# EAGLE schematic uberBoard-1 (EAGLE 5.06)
ABBREV: un1; PROJECT: UberNode v1
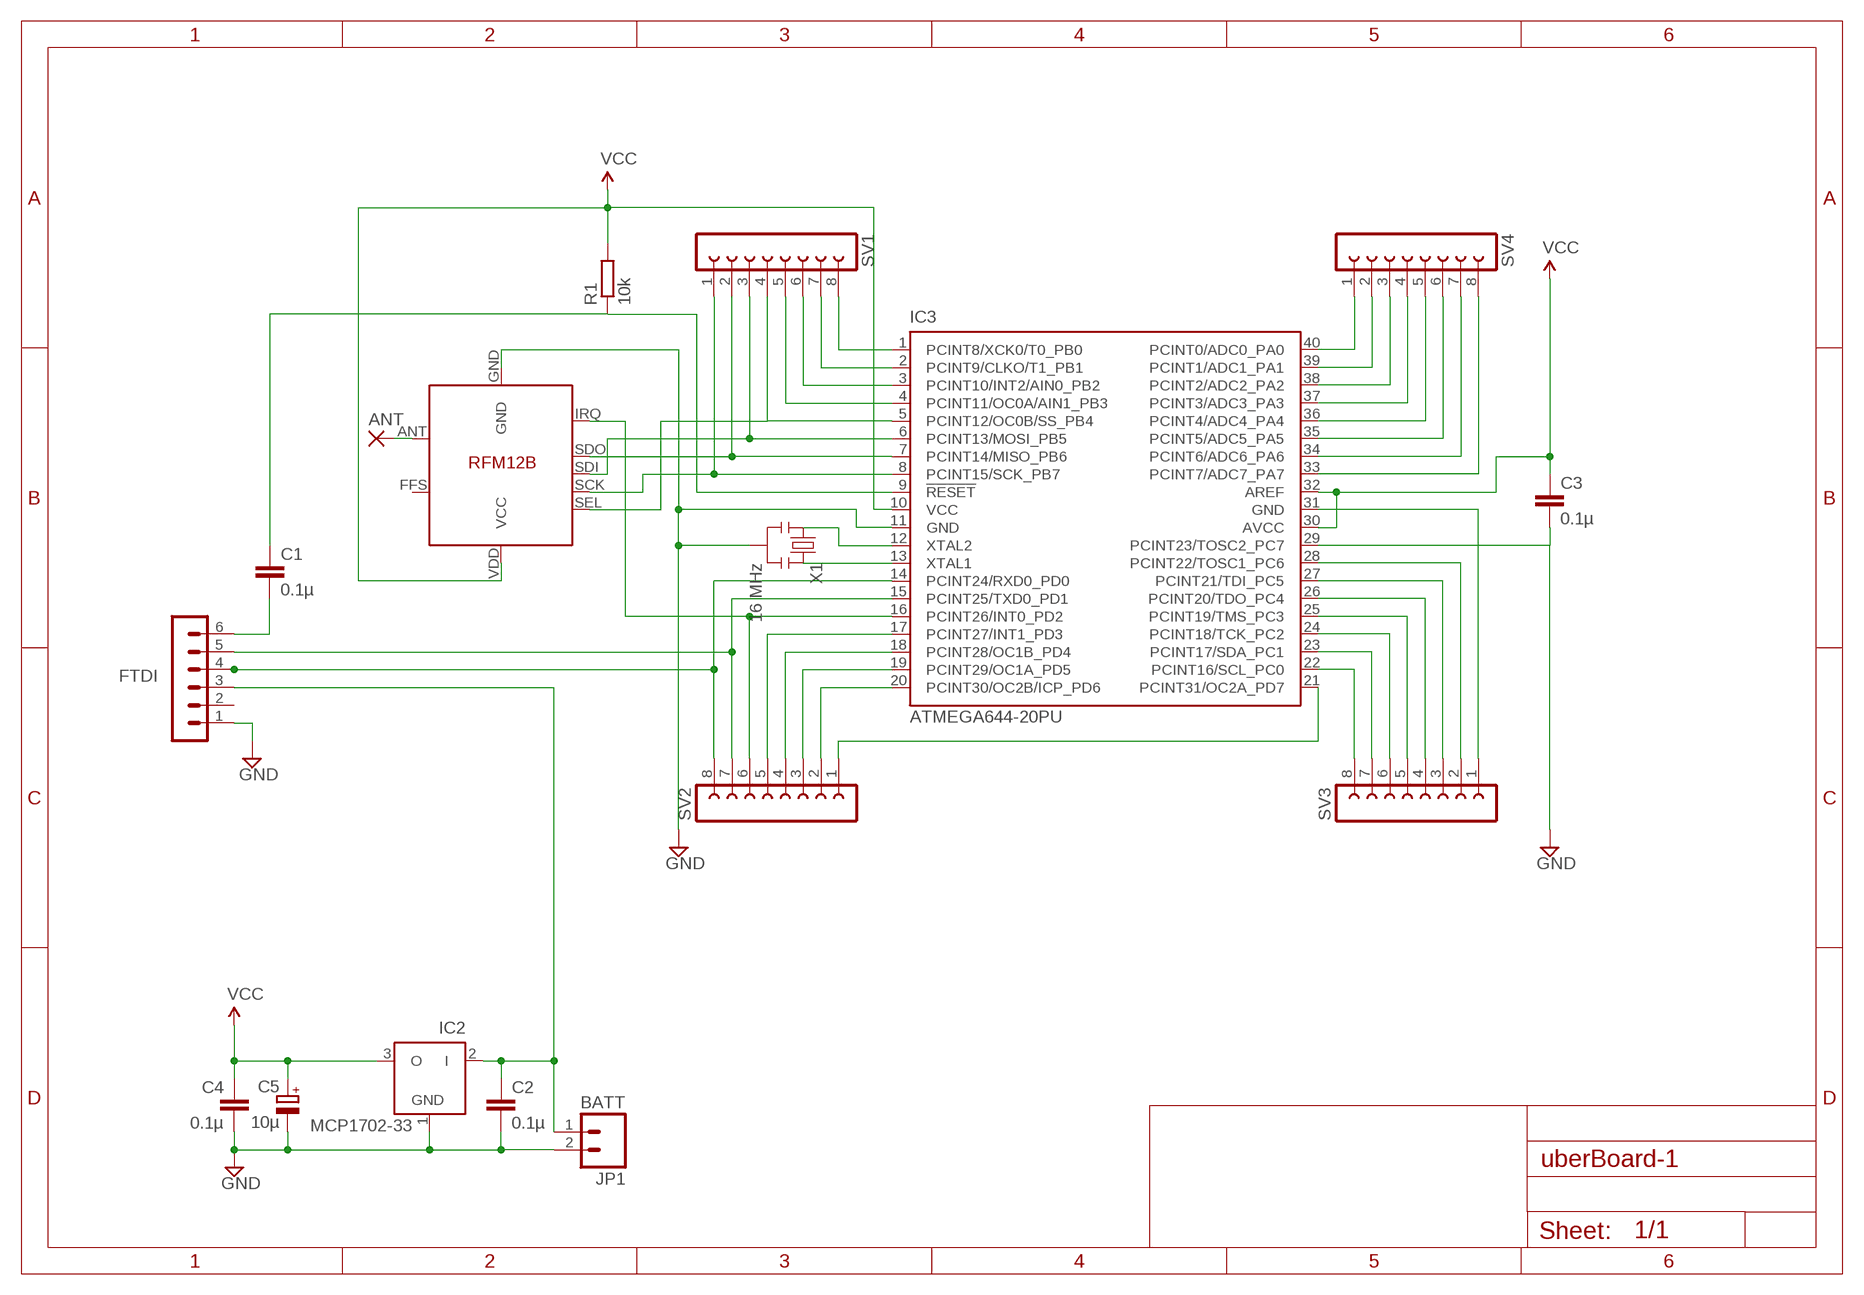
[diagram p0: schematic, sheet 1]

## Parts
ANT  1,6/0,8  [1,6/0,8]
C1  0.1µ  C-EU025-024X044  [C025-024X044]
C2  0.1µ  C-EU025-024X044  [C025-024X044]
C3  0.1µ  C-EU025-024X044  [C025-024X044]
C4  0.1µ  C-EU025-024X044  [C025-024X044]
C5  10µ  CPOL-EUE1.8-4  [E1,8-4]
FTDI  FTDI  MA06-1  [MA06-1]
IC2  MCP1702-33  MCP1702Z  [TO92]
IC3  ATMEGA644-20PU  [DIL40]
JP1  BATT  M02LOCK_LONGPADS  [1X02_LOCK_LONGPADS]
R1  10k  R-EU_0204/7  [0204/7]
SV1  FE08W  [FE08W]
SV2  FE08W  [FE08W]
SV3  FE08W  [FE08W]
SV4  FE08W  [FE08W]
U$1  RFM12B  [RFM12B]
X1  16 MHz  RESONATORPTH  [RESONATOR-PTH]

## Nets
GND [power]: C2.2 C3.2 C4.2 C5.- FTDI.1 IC2.1(GND) IC3.11(GND) IC3.31(GND) JP1.2 U$1.GND X1.2
N$1: IC3.13(XTAL1) X1.3
N$2: IC3.5(PCINT12/OC0B/SS_PB4) SV1.4 U$1.SEL
N$3: IC3.8(PCINT15/SCK_PB7) SV1.1 U$1.SCK
N$4: IC3.6(PCINT13/MOSI_PB5) SV1.3 U$1.SDI
N$5: IC3.7(PCINT14/MISO_PB6) SV1.2 U$1.SDO
N$6: IC3.16(PCINT26/INT0_PD2) SV2.6 U$1.IRQ
N$7: IC3.12(XTAL2) X1.1
N$8: IC3.29(PCINT23/TOSC2_PC7) SV3.1
N$9: IC3.28(PCINT22/TOSC1_PC6) SV3.2
N$10: IC3.27(PCINT21/TDI_PC5) SV3.3
N$11: IC3.26(PCINT20/TDO_PC4) SV3.4
N$12: IC3.25(PCINT19/TMS_PC3) SV3.5
N$13: ANT.1(P) U$1.ANT
N$14: IC3.24(PCINT18/TCK_PC2) SV3.6
N$15: IC3.23(PCINT17/SDA_PC1) SV3.7
N$16: IC3.22(PCINT16/SCL_PC0) SV3.8
N$17: IC3.40(PCINT0/ADC0_PA0) SV4.1
N$18: IC3.39(PCINT1/ADC1_PA1) SV4.2
N$19: IC3.38(PCINT2/ADC2_PA2) SV4.3
N$20: C1.2 FTDI.6
N$21: IC3.37(PCINT3/ADC3_PA3) SV4.4
N$22: IC3.36(PCINT4/ADC4_PA4) SV4.5
N$23: IC3.35(PCINT5/ADC5_PA5) SV4.6
N$24: IC3.34(PCINT6/ADC6_PA6) SV4.7
N$25: IC3.33(PCINT7/ADC7_PA7) SV4.8
N$26: IC3.20(PCINT30/OC2B/ICP_PD6) SV2.2
N$27: IC3.19(PCINT29/OC1A_PD5) SV2.3
N$28: IC3.18(PCINT28/OC1B_PD4) SV2.4
N$29: IC3.17(PCINT27/INT1_PD3) SV2.5
N$30: FTDI.5 IC3.15(PCINT25/TXD0_PD1) SV2.7
N$31: FTDI.4 IC3.14(PCINT24/RXD0_PD0) SV2.8
N$32: IC3.4(PCINT11/OC0A/AIN1_PB3) SV1.5
N$33: IC3.3(PCINT10/INT2/AIN0_PB2) SV1.6
N$34: IC3.2(PCINT9/CLKO/T1_PB1) SV1.7
N$35: IC3.1(PCINT8/XCK0/T0_PB0) SV1.8
N$36: IC3.21(PCINT31/OC2A_PD7) SV2.1
PWR [power]: C2.1 FTDI.3 IC2.2(I) JP1.1
RST: C1.1 IC3.9(!RESET) R1.1
VCC [power]: C3.1 C4.1 C5.+ IC2.3(O) IC3.10(VCC) IC3.30(AVCC) IC3.32(AREF) R1.2 U$1.VDD(VCC)
Unconnected: FTDI.2 U$1.FFS

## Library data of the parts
ANT = JeeLabs:1,6/0,8: THROUGH-HOLE PAD
C1-C4 = resistor:C-EU: CAPACITOR, European symbol
C5 = resistor:CPOL-EU: POLARIZED CAPACITOR, European symbol
FTDI = JeeLabs:MA06-1: PIN HEADER
IC2 = JeeLabs:MCP1702: 200 mA, Low Power Low Dropout Voltage Regulator
IC3 = atmel:ATMEGA644-*PU: 8-bit Microcontroller with 64K Bytes In-System Programmable Flash Auto generated by make-symbol-device-package-bsdl.ulp Rev. 34 Source: http://www.atmel.com/dyn/resources/prod_documents/doc2593.pdf; MPN: ATMEGA644-20PU; OC_FARNELL: 1288340; OC_NEWARK: 23M5060
JP1 = SparkFun:M02: Header 2
R1 = resistor:R-EU_: RESISTOR, European symbol
SV1-SV4 = con-lsta:FE08W: FEMALE HEADER; OC_FARNELL: unknown; OC_NEWARK: unknown
U$1 = JeeLabs:RFM12B
X1 = SparkFun:RESONATOR: Resonator Small SMD resonator. This is the itty bitty 10/20MHz resonators with built in caps. CSTCE10M0G55 and CSTCE20M0V53. Footprint has been reviewed closely but hasn't been tested yet.

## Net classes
1 power: width 0.381 mm, clearance 0.254 mm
